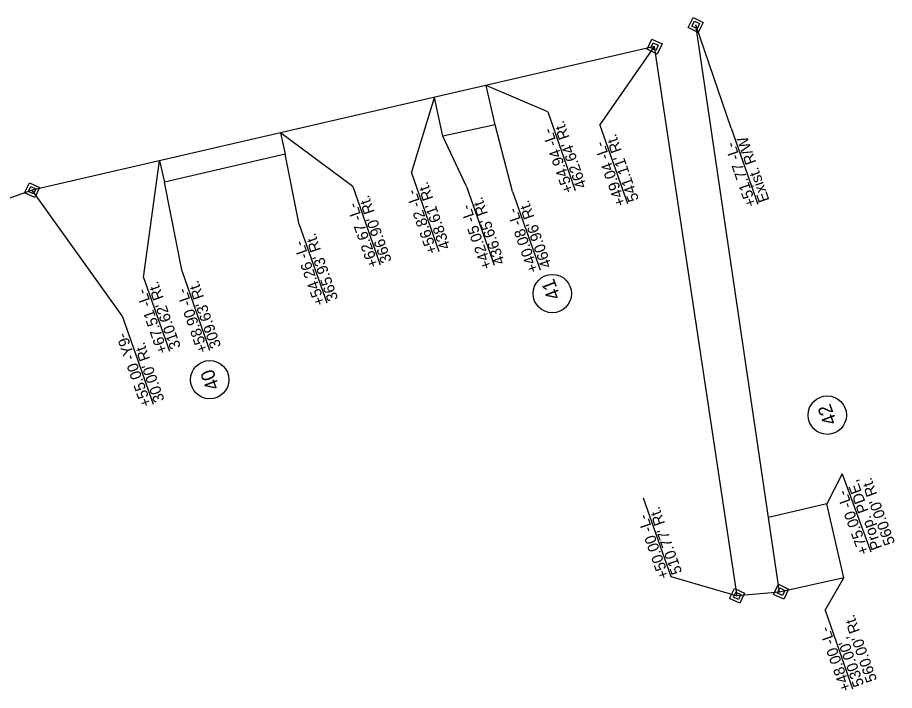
# Model space of a CAD drawing. Extents: x 1610947 to 1617684, y 899814 to 904658.
# Drawn here: x 1616822.3 to 1617221.9, y 902788 to 903094.7 of the extents above; entities that cross this region are included whole.
import ezdxf

# ---------------------------------------------------------------- set-up
doc = ezdxf.new("R2010")
doc.units = 0
for name, color, linetype in [('Prop Conc 1ft 6in Curb and Gutter', 7, 'Continuous'), ('Prop EOT Dash', 7, 'Continuous'), ('Prop Hatching', 7, 'Continuous'), ('Prop ROW Marker CELL', 7, 'Continuous'), ('Scratch_Level_3', 7, 'Continuous'), ('Scratch_Level_8', 7, 'Continuous'), ('Typical Terminator CELL', 7, 'Continuous')]:
    doc.layers.add(name, color=color, linetype=linetype)

msp = doc.modelspace()

# ---------------------------------------------------------------- linework, layer by layer
at = {"layer": 'Prop Conc 1ft 6in Curb and Gutter'}
for p, q in [((1617063.88, 903051.7), (1617076.42, 903015.92)), ((1617026.88, 903017.62), (1617016.06, 903040.57)), ((1617001.81, 903023.88), (1617014.35, 902988.1)), ((1616975.02, 903017.73), (1616987.55, 902981.94)), ((1617026.88, 903017.62), (1617039.42, 902981.83)), ((1617047.92, 903015.44), (1617060.45, 902979.65)), ((1616950.63, 903000.43), (1616963.16, 902964.64)), ((1616897.28, 902978.87), (1616909.82, 902943.08)), ((1616879.71, 902976.23), (1616891.46, 902942.7)), ((1617198.1, 902886.8), (1617191.1, 902873.04)), ((1617198.1, 902886.8), (1617211.1, 902851.18)), ((1617190.32, 902824.57), (1617198.81, 902839.35)), ((1617190.32, 902824.57), (1617202.86, 902788.78))]:
    msp.add_line(p, q, dxfattribs=at)
for points in [[(1617063.88, 903051.7), (1617035.79, 903063.71)], [(1617001.81, 903023.88), (1617012.27, 903058.29)], [(1617047.92, 903015.44), (1617039.92, 903045.81)], [(1616975.02, 903017.73), (1616942.07, 903042.1)], [(1616879.71, 902976.23), (1616886.95, 903029.39)], [(1616950.63, 903000.43), (1616944.31, 903032.36)], [(1616897.28, 902978.87), (1616889.19, 903019.65)]]:
    msp.add_lwpolyline(points, dxfattribs=at)
at = {"layer": 'Prop EOT Dash'}
for points in [[(1617127.95, 903090.09), (1617130.13, 903094.69), (1617134.73, 903092.5), (1617132.54, 903087.9)], [(1617129.64, 903090.69), (1617130.74, 903092.99), (1617133.03, 903091.9), (1617131.94, 903089.6)], [(1617109.21, 903080.22), (1617111.4, 903084.82), (1617115.99, 903082.63), (1617113.81, 903078.04)], [(1617110.91, 903080.82), (1617112, 903083.12), (1617114.3, 903082.03), (1617113.21, 903079.73)], [(1616825.51, 903014.8), (1616827.69, 903019.4), (1616832.29, 903017.21), (1616830.11, 903012.61)], [(1616827.2, 903015.4), (1616828.3, 903017.7), (1616830.6, 903016.61), (1616829.5, 903014.31)], [(1617146.81, 902829.93), (1617149, 902834.53), (1617153.6, 902832.34), (1617151.41, 902827.75)], [(1617166.87, 902831.81), (1617169.05, 902836.4), (1617173.65, 902834.22), (1617171.46, 902829.62)], [(1617168.56, 902832.41), (1617169.65, 902834.71), (1617171.95, 902833.61), (1617170.86, 902831.32)], [(1617148.51, 902830.54), (1617149.6, 902832.84), (1617151.9, 902831.74), (1617150.81, 902829.44)]]:
    msp.add_lwpolyline(points, close=True, dxfattribs=at)
at = {"layer": 'Prop Hatching'}
for centre in [(1617065.99, 902968.88), (1616909.87, 902929.62), (1617191.3, 902913.48)]:
    msp.add_circle(centre, 8.75, dxfattribs=at)
at = {"layer": 'Prop ROW Marker CELL'}
for p, q in [((1617131.34, 903091.29), (1617131.34, 903091.29)), ((1617112.6, 903081.43), (1617112.6, 903081.43)), ((1616828.9, 903016), (1616828.9, 903016)), ((1617150.21, 902831.14), (1617150.21, 902831.14)), ((1617170.26, 902833.01), (1617170.26, 902833.01))]:
    msp.add_line(p, q, dxfattribs=at)
at = {"layer": 'Scratch_Level_3'}
for p, q in [((1617039.92, 903045.81), (1617035.79, 903063.71)), ((1617016.06, 903040.57), (1617012.27, 903058.29)), ((1617039.92, 903045.81), (1617016.06, 903040.57)), ((1616942.07, 903042.1), (1616944.31, 903032.36)), ((1616886.95, 903029.39), (1616889.19, 903019.65)), ((1616944.31, 903032.36), (1616889.19, 903019.65)), ((1617191.1, 902873.04), (1617164.51, 902866.76)), ((1617198.81, 902839.35), (1617191.1, 902873.04)), ((1617198.81, 902839.35), (1617169.52, 902832.85))]:
    msp.add_line(p, q, dxfattribs=at)
at = {"layer": 'Scratch_Level_8'}
for p, q in [((1617087.66, 903045.66), (1617100.2, 903009.88)), ((1617147.58, 903044.29), (1617159.72, 903009.63)), ((1616869.92, 902958.76), (1616884.03, 902918.48)), ((1617107.4, 902875.79), (1617119.94, 902840.01))]:
    msp.add_line(p, q, dxfattribs=at)
for points in [[(1617147.58, 903044.29), (1617131.34, 903091.29)], [(1617087.66, 903045.66), (1617112.6, 903081.43)], [(1616869.92, 902958.76), (1616828.9, 903016)], [(1617119.94, 902840.01), (1617150.21, 902831.14)]]:
    msp.add_lwpolyline(points, dxfattribs=at)
at = {"layer": 'Typical Terminator CELL'}
for p, q in [((1617169.52, 902832.85), (1617131.34, 903091.29)), ((1617112.6, 903081.43), (1616828.9, 903016)), ((1617150.21, 902831.14), (1617112.6, 903081.43)), ((1616828.9, 903016), (1616708.61, 902973.81)), ((1617169.52, 902832.85), (1617150.21, 902831.14))]:
    msp.add_line(p, q, dxfattribs=at)

# ---------------------------------------------------------------- texts
at = {"layer": 'Prop Conc 1ft 6in Curb and Gutter'}
for s, rotation, p in [("462.64' Rt.", 109.3048, (1617081.72, 903017.78)), ('+54.94 -L-', 109.3048, (1617075.83, 903015.71)), ("438.61' Rt.", 109.3048, (1617019.65, 902989.96)), ("366.90' Rt.", 109.3048, (1616992.86, 902983.8)), ('+56.82 -L-', 109.3048, (1617013.76, 902987.89)), ('+62.67 -L-', 109.3048, (1616986.96, 902981.74)), ("436.65' Rt.", 109.3048, (1617044.5, 902983.03)), ("460.96' Rt.", 109.3048, (1617065.76, 902981.51)), ('+42.05 -L-', 109.3048, (1617038.6, 902980.97)), ('+40.08 -L-', 109.3048, (1617059.86, 902979.44)), ("365.93' Rt.", 109.3048, (1616968.47, 902966.5)), ('+54.26 -L-', 109.3048, (1616962.57, 902964.43)), ("310.62' Rt.", 109.3048, (1616896.77, 902944.56)), ("309.63' Rt.", 109.3048, (1616915.12, 902944.94)), ('+67.51 -L-', 109.3048, (1616890.87, 902942.5)), ('+58.90 -L-', 109.3048, (1616909.23, 902942.88)), ('Prop. PDE,', 110.0511, (1617216.39, 902853.11)), ("560.00' Rt.", 110.0511, (1617222.26, 902855.25)), ('+75.00 -L-', 110.0511, (1617210.52, 902850.96)), ("560.00' Rt.", 109.3048, (1617214.07, 902792.71)), ('+48.00 -L-', 109.3048, (1617202.27, 902788.58)), ("530.00',", 109.3048, (1617208.17, 902790.64))]:
    msp.add_text(s, height=5, rotation=rotation, dxfattribs=at).set_placement(p)
at = {"layer": 'Prop Hatching'}
for s, p in [('41', (1617069.9, 902967.35)), ('40', (1616914.48, 902926.2)), ('42', (1617195.83, 902910.28))]:
    msp.add_text(s, height=6.25, rotation=110.4882, dxfattribs=at).set_placement(p)
at = {"layer": 'Scratch_Level_8'}
for s, p in [("541.11' Rt.", (1617105.51, 903011.74)), ('+49.04 -L-', (1617099.61, 903009.67)), ('+51.77 -L-', (1617159.13, 903009.42)), ('Exist. R/W', (1617165.02, 903011.49)), ('+55.00 -Y9-', (1616883.44, 902918.27)), ("30.00' Rt.", (1616889.34, 902920.34)), ("510.77' Rt.", (1617125.24, 902841.87)), ('+50.00 -L-', (1617119.35, 902839.8))]:
    msp.add_text(s, height=5, rotation=109.3048, dxfattribs=at).set_placement(p)

doc.saveas('drawing.dxf')
